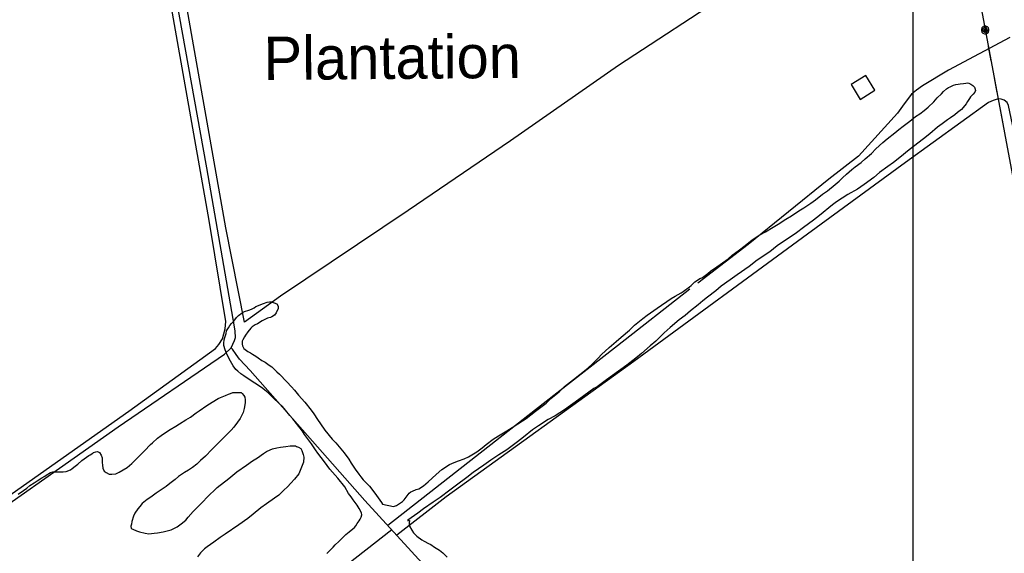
# Model space of a CAD drawing. Extents: x 3281947 to 3319794, y 715894 to 741249.
# Drawn here: x 3289265 to 3291541, y 730987 to 732220 of the extents above; entities that cross this region are included whole.
import ezdxf

# ---------------------------------------------------------------- set-up
doc = ezdxf.new("R2010")
doc.units = 0
for name, color, linetype in [('V-BLDG-IDEN', 7, 'Continuous'), ('V-BLDG-OTLN', 7, 'Continuous'), ('V-DTCH-CNTR', 7, 'Continuous'), ('V-GRID-MAJR', 7, 'Continuous'), ('V-SITE-VEGE', 7, 'Continuous'), ('V-TOPO-SHOR', 7, 'Continuous'), ('V-UTIL-LINE', 7, 'Continuous')]:
    doc.layers.add(name, color=color, linetype=linetype)

msp = doc.modelspace()

# ---------------------------------------------------------------- linework, layer by layer
at = {"layer": 'V-BLDG-OTLN'}
msp.add_lwpolyline([(3291241.7, 732057.2), (3291220.7, 732091.2), (3291186.7, 732070.2), (3291207.7, 732036.2)], close=True, dxfattribs=at)
at = {"layer": 'V-DTCH-CNTR'}
for points in [[(3289046.9, 730995.6), (3289060.9, 730992.5), (3289194.8, 731088), (3289517.9, 731315.2), (3289717.8, 731460.6), (3289725.7, 731469.9), (3289734.2, 731482.7), (3289740.2, 731505.9), (3289741.7, 731522.8), (3289703, 731756), (3289607.9, 732297.1), (3289521.9, 732726.9), (3289434, 733216.7), (3289344.7, 733721.6), (3289306.8, 733950.3)], [(3291456, 732650.3), (3291154.2, 732449.4), (3290909.1, 732285), (3290649.5, 732114.7), (3290399.4, 731940.4), (3290163.3, 731779.5), (3289868.1, 731581.4), (3289785.3, 731521.4), (3289741.6, 731739.6), (3289671.4, 732135.7), (3289606.9, 732504.1), (3289571.2, 732730.6), (3289755, 732848.6), (3290081.9, 733072.3), (3290303.4, 733228.4), (3290541.8, 733385.2), (3290824.5, 733578.8), (3291082.2, 733757.6), (3291194.3, 733831)]]:
    msp.add_lwpolyline(points, dxfattribs=at)
at = {"layer": 'V-GRID-MAJR'}
msp.add_spline([(3291333.3, 721274), (3291331.5, 727333.8), (3291329.7, 733395.6), (3291328, 739457.3), (3291328, 739459.2)], degree=3, dxfattribs=at)
at = {"layer": 'V-SITE-VEGE'}
for points in [[(3290279.5, 731200.5), (3290293, 731205.7), (3290302.3, 731209.8), (3290314.1, 731216.8), (3290321.7, 731221.7), (3290334, 731231.2), (3290343.4, 731238.2), (3290359.5, 731250.6), (3290372.1, 731258.4), (3290391.2, 731270.3), (3290403.8, 731277.7), (3290427.1, 731292.9), (3290435.6, 731298.7), (3290457.6, 731315.2), (3290466.5, 731322.6), (3290481.8, 731334.2), (3290493.2, 731344.9), (3290511.9, 731360.6), (3290524.2, 731372.2), (3290545.4, 731388.7), (3290578.4, 731414.7), (3290589.1, 731424.7), (3290602.2, 731437.9), (3290609.9, 731446.6), (3290628.1, 731462.8), (3290644.3, 731476.4), (3290655.3, 731486.3), (3290674.4, 731502.8), (3290686.3, 731514.4), (3290705.3, 731529.7), (3290715.5, 731537.5), (3290730.8, 731548.3), (3290738.4, 731554), (3290771.4, 731576.3), (3290780.3, 731581.2), (3290794.2, 731589.4), (3290798.9, 731592.3), (3290813.7, 731603), (3290817.5, 731605.9), (3290826, 731614.1), (3290831.9, 731618.7), (3290837, 731622), (3290841.6, 731623.6), (3290846.7, 731626.9), (3290856, 731633.9), (3290862, 731639.3), (3290876.4, 731649.1), (3290902.6, 731667.7), (3290912.4, 731675.9), (3290928.9, 731688.7), (3290939, 731696.2), (3290954.7, 731708.5), (3290960.2, 731712.7), (3290976.3, 731722.9), (3290989, 731729.9), (3291006.7, 731740.6), (3291018.6, 731747.6), (3291035.9, 731759.1), (3291049, 731767.3), (3291066.4, 731778.4), (3291077.4, 731785.8), (3291093.9, 731796.5), (3291104.5, 731803.9), (3291121, 731816.7), (3291132.4, 731825), (3291149.8, 731839.4), (3291159.5, 731847.3), (3291167.2, 731855.1), (3291176.1, 731863.4), (3291188.4, 731874.1), (3291196.5, 731879.9), (3291210.4, 731890.2), (3291219.4, 731898.5), (3291233.8, 731911.3), (3291244.4, 731921.7), (3291260.1, 731936.6), (3291270.3, 731945.2), (3291287.7, 731958.9), (3291297.4, 731966.3), (3291307.6, 731974.5), (3291322.4, 731986.1), (3291335.6, 731996.8), (3291345.7, 732003), (3291355.5, 732010.8), (3291365.2, 732017.8), (3291378.4, 732030.7), (3291386, 732039.4), (3291395.8, 732049.3), (3291400.5, 732054.7), (3291407.3, 732060.5), (3291411.9, 732063.4), (3291415.7, 732065), (3291423.3, 732068.7), (3291428.8, 732070.3), (3291434.7, 732071.5), (3291439.3, 732071.8), (3291446.9, 732073), (3291452.3, 732073.3), (3291456.1, 732074.1), (3291459, 732073.3), (3291464, 732071.1)], [(3291464, 732071.1), (3291468.2, 732068.1), (3291471.9, 732064.3), (3291473.1, 732061.8), (3291474.3, 732056.7), (3291473, 732052.9), (3291469.2, 732048.4), (3291463.2, 732041.7), (3291460.7, 732038.4), (3291456, 732031.3), (3291452.5, 732025.9), (3291446.1, 732017.6), (3291442.3, 732013.1), (3291432.6, 732005.6), (3291427, 732000.3), (3291416.9, 731993.7), (3291409.7, 731989.2), (3291397.4, 731979.7), (3291386.8, 731971.8), (3291368.6, 731956.6), (3291354.6, 731945), (3291331.3, 731927.3), (3291317.3, 731916.1), (3291303.7, 731905), (3291284.7, 731890.5), (3291272, 731881), (3291252.9, 731867.4), (3291239.8, 731855.4), (3291217.3, 731839.4), (3291201.7, 731828.7), (3291179.7, 731816.4), (3291153.5, 731799.5), (3291143.7, 731792.1), (3291114.1, 731767.7), (3291100.1, 731757), (3291077.2, 731739.7), (3291060.7, 731728.1), (3291016.2, 731697.7), (3290998.9, 731684.1), (3290969.7, 731664.3), (3290951, 731649.9), (3290923.9, 731630.5), (3290907.4, 731619), (3290886.3, 731604.6)], [(3290886.3, 731604.6), (3290874.4, 731593.8), (3290855.3, 731579.4), (3290844.3, 731570.7), (3290833.7, 731561.2), (3290815.5, 731547.2), (3290803.2, 731536.8), (3290789.2, 731526.9), (3290768.4, 731509.2), (3290754.8, 731496.4), (3290735.7, 731477.7), (3290722.6, 731466.6), (3290702.6, 731449.2), (3290689.5, 731438), (3290668.7, 731422), (3290635.3, 731398.1), (3290621.3, 731387.8), (3290599.7, 731372.1), (3290592.5, 731367.6), (3290557.8, 731342.9), (3290538.3, 731328.4), (3290524.3, 731319), (3290502.8, 731305), (3290486.7, 731296), (3290464.7, 731282), (3290450.3, 731272.1), (3290430, 731255.6), (3290415.6, 731244.4), (3290391, 731226.3), (3290372.8, 731214.8), (3290354.2, 731202.4), (3290337.7, 731190.9), (3290313.6, 731173.6), (3290298.8, 731162.5), (3290274.6, 731144.7), (3290259.8, 731133.2), (3290236.9, 731116.3), (3290221.2, 731105.2), (3290198.8, 731089.5), (3290185.7, 731079.6), (3290170.4, 731068.9), (3290164.5, 731065.2), (3290162, 731063.1), (3290166.2, 731062.7), (3290165.3, 731056.8), (3290166, 731050.1), (3290171.8, 731040.8), (3290175.9, 731034.4), (3290183.3, 731026.8), (3290195, 731018.3), (3290200.4, 731015.2), (3290209.9, 731009.7), (3290215.8, 731007.5), (3290224.1, 731001.5), (3290235.8, 730994.2), (3290243.2, 730988.3), (3290253.2, 730978.1)], [(3289743.7, 731449.4), (3289740, 731457), (3289737.2, 731467.1), (3289736.9, 731472.6), (3289738.2, 731480.5), (3289739.6, 731485.6), (3289742.6, 731495.2), (3289743.5, 731501), (3289747.8, 731508.1), (3289750.8, 731513.5), (3289755.1, 731518.5), (3289760.2, 731523.9), (3289766.6, 731532.2), (3289770.9, 731536.7), (3289779.7, 731542.5), (3289785.2, 731545.8), (3289794.9, 731549), (3289800.8, 731551.5), (3289807.2, 731554.7), (3289811.4, 731557.2), (3289828.7, 731564.5), (3289837.1, 731567.3), (3289842.6, 731568.1), (3289847.2, 731568.1), (3289859.7, 731563.7), (3289862.6, 731558.6), (3289862.5, 731552.8), (3289858.2, 731542.7), (3289853.9, 731537.8), (3289848, 731533.6), (3289845, 731532.4), (3289841.3, 731531.6), (3289838.3, 731530.8), (3289826.1, 731524.3), (3289814.7, 731517.7), (3289809.2, 731514.9), (3289802.4, 731510.3), (3289799.4, 731507.4), (3289793, 731498.7), (3289787.5, 731491.6), (3289784.9, 731487.5), (3289781, 731480.8), (3289779.7, 731477.5), (3289779.6, 731470.8), (3289780, 731466.2), (3289783.7, 731460.2), (3289792.8, 731453.4), (3289798.7, 731450.4), (3289803.7, 731447.4), (3289811.2, 731442.7), (3289816.6, 731438.8), (3289825.3, 731432.9), (3289832.4, 731428.6), (3289841.9, 731422.2), (3289847.8, 731417.9), (3289854.8, 731411.1), (3289859.4, 731406.8), (3289866, 731400.9), (3289883, 731383.4), (3289893.3, 731372), (3289900.8, 731363.9), (3289909.8, 731352.9), (3289924.7, 731336.3), (3289938.8, 731317.7), (3289945.4, 731309.2), (3289954, 731296.1), (3289960.6, 731286.4), (3289970.9, 731271.6), (3289987.4, 731251.2), (3289995.7, 731242.7), (3290007.2, 731228.7), (3290015.5, 731219.4), (3290025.8, 731205), (3290031.6, 731195.3), (3290041, 731181.7), (3290049.3, 731170.3), (3290053.8, 731163.5), (3290059.2, 731157.2), (3290068.3, 731147.8), (3290073.6, 731141.9), (3290083.5, 731128.8), (3290090.1, 731120.3), (3290097.6, 731110.1), (3290101.3, 731104.2), (3290104.2, 731100.8), (3290129.3, 731095), (3290136.4, 731097.5), (3290150, 731106.5), (3290154.2, 731110.6), (3290165.7, 731126), (3290169.5, 731129.3), (3290173.3, 731130.5), (3290181.8, 731134.2), (3290187.7, 731136.2), (3290198.7, 731143.2), (3290209.3, 731152.3), (3290227.9, 731169.3), (3290240.7, 731180.4), (3290258.4, 731192.4), (3290269.4, 731197.2), (3290279.5, 731200.5)], [(3289975.2, 730986.7), (3289981.1, 730992.5), (3289989.6, 731001.2), (3289994.3, 731006.6), (3290002.8, 731014), (3290009.2, 731020.7), (3290019.4, 731030.6), (3290026.6, 731036.4), (3290035, 731043.4), (3290039.3, 731047.1), (3290042.3, 731050.4), (3290045.3, 731055.8), (3290050, 731062.1), (3290052.1, 731065.8), (3290054.3, 731070.4), (3290056, 731076.3), (3290055.2, 731080.5), (3290050.3, 731090.6), (3290045.4, 731098.6), (3290035.9, 731110.5), (3290031.8, 731117.3), (3290025.6, 731125.3), (3290016.6, 731140.5), (3290000.5, 731160.9), (3289982.3, 731181.7), (3289975.7, 731190.1), (3289969.5, 731198.6), (3289954.7, 731218.5), (3289948.9, 731226.6), (3289939.8, 731239.7), (3289933.2, 731249), (3289923.8, 731261.3), (3289918.8, 731269.3), (3289910.6, 731279.9), (3289905.2, 731287.1), (3289896.6, 731298.1), (3289889.5, 731305.3), (3289879.6, 731317.6), (3289872.6, 731326.1), (3289864.3, 731333.8), (3289852.7, 731345.2), (3289839.9, 731357.6), (3289832, 731364), (3289827, 731367.8), (3289817, 731375.1), (3289800.4, 731385.8), (3289783.3, 731397.3), (3289776.7, 731402), (3289769.2, 731408), (3289765, 731411.8), (3289758.9, 731420.7), (3289749.4, 731436.8), (3289743.7, 731449.4)], [(3289673.6, 731311.5), (3289680.3, 731316), (3289698.1, 731328.4), (3289710.4, 731336.6), (3289724.3, 731344.8), (3289729.4, 731346.8), (3289737, 731350.5), (3289741.2, 731352.1), (3289748, 731355), (3289752.2, 731356.6), (3289758.1, 731358.6), (3289762.3, 731359), (3289773.2, 731358.9), (3289776.9, 731358.4), (3289779.8, 731356.3), (3289783.1, 731352), (3289785.6, 731348.2), (3289786.4, 731341.9), (3289786.3, 731334.8), (3289784, 731321.8), (3289782.2, 731312.6), (3289774.9, 731298.9), (3289768.9, 731290.5), (3289760, 731278.9), (3289754, 731271.9), (3289744.2, 731261.5), (3289735.7, 731253.2), (3289720, 731237.5), (3289709.4, 731226.7), (3289694.5, 731211.4), (3289683.5, 731201.5), (3289674.5, 731192.8), (3289664.4, 731185.3), (3289655.5, 731179.6), (3289646.2, 731173.8), (3289632.7, 731164.4), (3289625, 731157.7), (3289612.7, 731148.7), (3289603.8, 731141.7), (3289589.9, 731132.2), (3289581, 731126), (3289568.7, 731116.9), (3289560.2, 731111.2), (3289548.8, 731102.1), (3289542.8, 731095), (3289538.6, 731089.7), (3289531.7, 731080.1), (3289528.7, 731073), (3289524.4, 731060.9), (3289523.8, 731054.2), (3289522.5, 731049.6), (3289523.3, 731044.5), (3289526.6, 731042.8), (3289535, 731039.4), (3289542.1, 731036.8), (3289555, 731033.6), (3289563.8, 731032.3), (3289576.4, 731033.4), (3289583.6, 731034.5), (3289596.6, 731036.5), (3289615.5, 731041.7), (3289629.5, 731048.6), (3289638.8, 731055.2), (3289649, 731063.5), (3289654.9, 731070.9), (3289666.4, 731083.4), (3289674.9, 731092.1), (3289689.4, 731106.6), (3289697.9, 731116.1), (3289721.7, 731139.3), (3289748.8, 731160.3), (3289767.4, 731175.2), (3289789.5, 731190.9), (3289803.8, 731200.7), (3289814.9, 731208.1), (3289829.2, 731217.6), (3289835.6, 731222.1), (3289844.5, 731226.6), (3289849.9, 731228.7), (3289860, 731230.6), (3289868, 731232.6), (3289880.2, 731234.2), (3289890.3, 731235.3), (3289897.4, 731235.6), (3289902.9, 731235.5), (3289905.4, 731234.2), (3289909.5, 731232.5), (3289915.4, 731229.1), (3289917.4, 731224.9), (3289920.2, 731215.2), (3289922.2, 731209.3), (3289921.3, 731197.5), (3289913.9, 731178.3), (3289910.4, 731170.8), (3289900.2, 731158.4), (3289891.7, 731149.3), (3289884.5, 731141), (3289876, 731132.7), (3289864.1, 731121.5), (3289853.9, 731114.5), (3289835.7, 731101.3)], [(3289261.7, 731123.8), (3289274, 731132.1), (3289281.6, 731137.9), (3289288.8, 731143.6), (3289298.6, 731150.2), (3289305.8, 731154.3), (3289316.3, 731161.3), (3289323.1, 731165.4), (3289326.5, 731167.9), (3289336.2, 731173.6), (3289341.7, 731175.2), (3289348, 731175.6), (3289366, 731175.4), (3289372.7, 731176.5), (3289382.4, 731180.2), (3289386.7, 731183.1), (3289393.4, 731188.8), (3289399.4, 731193.4), (3289408.7, 731201.6), (3289425.2, 731212.8), (3289428.2, 731214.4), (3289434.1, 731218.5), (3289436.2, 731220.2), (3289441.3, 731221.8), (3289444.2, 731222.6), (3289447.1, 731221.7), (3289449.6, 731220), (3289453.3, 731213.7), (3289455.8, 731207.8), (3289456.1, 731196.8), (3289456.8, 731191), (3289457.2, 731184.2), (3289460.8, 731177.1), (3289465, 731173.7), (3289472.5, 731169.8), (3289478.4, 731169.7), (3289487.2, 731170.9), (3289491, 731172.1), (3289495.6, 731174.9), (3289513.8, 731185.6), (3289524.4, 731194.3), (3289541.8, 731211.3), (3289553.7, 731223.7), (3289567.8, 731238.6), (3289572, 731242.7), (3289583.9, 731253.5), (3289592.4, 731259.3), (3289605, 731267.5), (3289613.1, 731273.3), (3289626.6, 731280.6), (3289634.6, 731286.4), (3289649, 731295.9), (3289660, 731302), (3289673.6, 731311.5)], [(3289835.7, 731101.3), (3289822.6, 731092.3), (3289804.8, 731077.4), (3289792.9, 731067.9), (3289772.2, 731052.7), (3289740, 731031.3), (3289728.6, 731023.9), (3289713.8, 731013.1), (3289698.9, 731002), (3289692.6, 730997.5), (3289683.2, 730987.9), (3289676, 730978.8)]]:
    msp.add_lwpolyline(points, dxfattribs=at)
at = {"layer": 'V-TOPO-SHOR'}
for points in [[(3289754.2, 731462.2), (3289761.9, 731478.7), (3289763.9, 731485.9), (3289763.5, 731500.7), (3289761.5, 731510.5), (3289697.7, 731878), (3289620.3, 732311.2), (3289551.8, 732686.5)], [(3291553.9, 732178.8), (3291412.2, 732103.7), (3291352.1, 732067.5), (3291337.8, 732057.3), (3291326.3, 732048.3), (3291309.3, 732025.5), (3291294.1, 732003.9), (3291204, 731905.2)], [(3291584.1, 731864.7), (3291551, 732022), (3291547.8, 732029.3), (3291540.8, 732034.7), (3291534, 732036.6), (3291527.1, 732037.2), (3291515.2, 732033.8), (3291504.7, 732029.3), (3291312.5, 731889.9), (3291085.9, 731725), (3290684.6, 731430.3), (3290251.4, 731117.8), (3290137.1, 731028.7)], [(3291204, 731905.2), (3291135.6, 731851.5), (3290949.2, 731701), (3290832.5, 731611.3)], [(3290814.5, 731597.9), (3290647.3, 731466.3), (3290475.2, 731332.6), (3290116.5, 731051.1)], [(3289035.7, 730956.2), (3289098.5, 731001.8), (3289492.7, 731279.3), (3289738.9, 731447.1), (3289754.2, 731462.2)], [(3290386.7, 730755.9), (3290063.2, 731109.4), (3289797.8, 731409.2), (3289773.1, 731435.4), (3289765.5, 731446.9), (3289757.1, 731458.5), (3289754.2, 731462.2)], [(3290125.5, 731041.3), (3289945.3, 730900.3), (3289653.5, 730669.3), (3289613.3, 730638.1)]]:
    msp.add_lwpolyline(points, dxfattribs=at)
at = {"layer": 'V-UTIL-LINE'}
for points in [[(3290106.1, 739458.5), (3290330.7, 738283.9), (3290559.1, 737084), (3290785.9, 735894.2), (3290899.5, 735297.4), (3291017.3, 734692.5), (3291128.9, 734105.7), (3291356.8, 732913.2), (3291474.1, 732317.9), (3291585.8, 731719.9), (3291701.1, 731121.7), (3291817.6, 730525.1), (3291929.6, 729931.5)], [(3291496.7, 732196.7), (3291498.8, 732198.7), (3291496.5, 732199.1), (3291494.6, 732197.1), (3291495.4, 732194.3), (3291498.8, 732194.8), (3291501.5, 732198.6), (3291499.1, 732202.1), (3291494.2, 732202.5), (3291491.5, 732198.9), (3291491.3, 732194.4), (3291495, 732191.3), (3291500.5, 732192), (3291505.6, 732198.4), (3291504.3, 732201.6), (3291501.8, 732204.1), (3291498.6, 732205.5), (3291495.1, 732205.6), (3291491.8, 732204.2), (3291489.3, 732201.8), (3291487.9, 732198.6), (3291487.9, 732195.1), (3291489.2, 732191.8), (3291491.6, 732189.3), (3291494.9, 732187.9), (3291498.4, 732187.9), (3291501.6, 732189.2), (3291504.2, 732191.6), (3291505.5, 732194.8), (3291505.6, 732198.4)], [(3291503.9, 732158.4), (3291510.1, 732125)], [(3291517.5, 732085.6), (3291523.7, 732052.2)], [(3291531.1, 732012.9), (3291537.3, 731979.5)]]:
    msp.add_lwpolyline(points, dxfattribs=at)

# ---------------------------------------------------------------- texts
at = {"layer": 'V-BLDG-IDEN'}
msp.add_text('Plantation', height=100, rotation=0.4943, dxfattribs=at).set_placement((3289829.4, 732080.7))

doc.saveas('drawing.dxf')
